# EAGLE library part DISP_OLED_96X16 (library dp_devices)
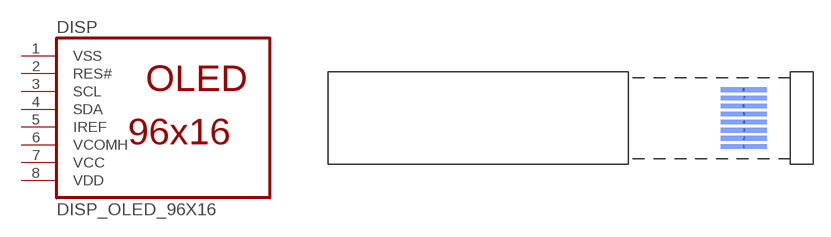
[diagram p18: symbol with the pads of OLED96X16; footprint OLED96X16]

Designator prefix DISP

## DISP_OLED_96X16  [OLED96X16]
1  VSS
2  RES#
3  SCL
4  SDA
5  IREF
6  VCOMH
7  VCC
8  VDD

## Footprint OLED96X16 (pad centres in mm)
smd 4 x 0.4 bottom: 1 0,-2.45; 2 0,-1.75; 3 0,-1.05; 4 0,-0.35; 5 0,0.35; 6 0,1.05; 7 0,1.75; 8 0,2.45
